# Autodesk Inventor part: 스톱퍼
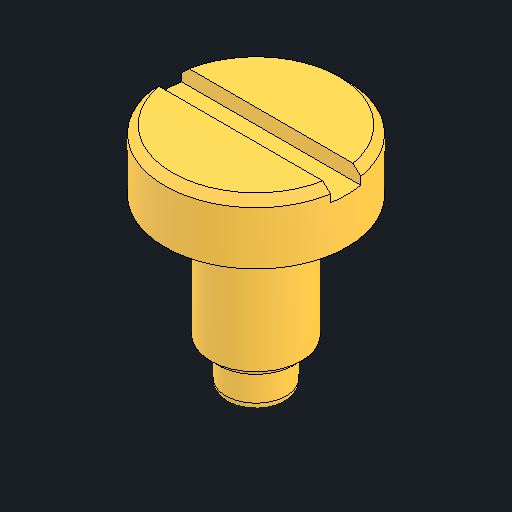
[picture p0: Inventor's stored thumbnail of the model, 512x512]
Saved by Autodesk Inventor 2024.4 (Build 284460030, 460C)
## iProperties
Created: 2026-08
Part Number: 스톱퍼
Material: 스테인리스강
Document SubType Name: Modeling
Designer: user
Density: 8.08 g/cm^3
Appearance: 기본값
Author: jhkim
Sending System: Autodesk Inventor 2027
Preprocessor: ST-DEVELOPER v20.1
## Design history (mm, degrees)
feature "솔리드1"
node "솔리드2"
